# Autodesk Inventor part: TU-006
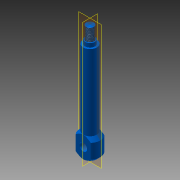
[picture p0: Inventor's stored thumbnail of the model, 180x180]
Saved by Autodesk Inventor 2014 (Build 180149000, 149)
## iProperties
Shininess: 64.0
Angle Display Precision: 2
Document Length Units: 11269
Document Angle Units: 11279
Document Time Units: 11290
Document Mass Units: 11286
Document Length Units Precision: 3
Document Angle Units Precision: 2
Compacted: True
Created: 2002-07
Part Number: TU-006
Document SubType Name: Modeling
Designer: PN
Description: Piston Rod
Density: 8.08 g/cm^3
Mass: 144.065 g
Surface Area: 58.412 cm^2
Volume: 17.8299 cm^3
Material: Stainless Steel
Appearance: 0,128,255
Density: 0.0
Volumn: 0.0
Area: 0.0
PropertySet Name: Model Information
Control State: 0
Master: False
Checked Out: False
LENGTH: 1.000 in
Author: PN
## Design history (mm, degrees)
sketch "Sketch1"
  geometry: L1 (0, 117)-(4, 117); L2 (10.5, 0)-(0, 0); L3 (7, 100)-(7, 22); L4 (5, 100)-(7, 100); L5 (5, 104)-(5, 100); L6 (4, 104)-(5, 104); L7 (4, 117)-(4, 104); L8 (10.5, 22)-(10.5, 0); L9 (0, 117)-(0, 0); L10 (7, 22)-(10.5, 22); 1 further point
  constraints: 20 end point, 6 parallel, 3 perpendicular, 1 coincident, 1 vertical
  dimensions: "d10" = 21 diameter of L8 L9; "d11" = 14 diameter of L3 L9; "d12" = 22 distance of L8.start L2.start; "d13" = 100 distance from line of L3.start L2; "d14" = 104 distance between parallel lines of L6 L2; "d15" = 117 distance between parallel lines of L2 L1; "d16" = 8 diameter of L7 L9; "d17" = 10 diameter of L5 L9
revolve "Revolution1" sketch "Sketch1" stored, may be unused: angle "d0" = 90 deg
sketch "Sketch2"
  geometry: L1 (-10.5, 22)-(-10.5, 0) reference; L2 (10.5, 22)-(10.5, 0) reference; L3 (-10.5, 11)-(10.5, 11); C1 r 4 at (0, 11)
  constraints: 3 midpoint, 2 end point, 1 centre point
  dimensions: "d1" = 8 diameter of C1
sketch "Sketch3"
  geometry: 2 further points
hole "Hole1" sketch "Sketch3" at (0, 0) diameter "d25" = 8; stored, may be unused: countersink angle "d29" = 90 deg, drill point angle "d31" = 118 deg; dims "d26" = 6, "d27" = 4, "d28" = 2, "d30" = 8
mirror "Mirror1"
chamfer "Chamfer1" distance "d18" = 3.5; stored, may be unused: second distance "d19" = 2, angle "d20" = 45 deg
body "Solid1"
workplane "Work Plane1"
workplane "Work Plane2"
sketch "Sketch4"
  geometry: L1 (-10.5, -39)-(10.5, -39) reference; L2 (-10.5, -61)-(10.5, -61) reference; L3 (-10.5, -61)-(-10.5, -39); L4 (10.5, -61)-(10.5, -39); 1 further point
  constraints: 4 end point, 1 parallel, 1 perpendicular
extrude "Extrusion1" cut sketch "Sketch4" stored distance "d21" = 10; taper "d22" = 0 deg
thread "Thread1" dims "d23" = 10, "d24" = 0
other parameters: "LENGTH" = 25.4 [user parameter]
